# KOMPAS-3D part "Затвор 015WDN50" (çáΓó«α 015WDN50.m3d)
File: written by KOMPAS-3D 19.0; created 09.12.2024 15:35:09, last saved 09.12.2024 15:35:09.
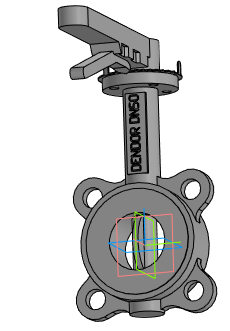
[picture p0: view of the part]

Document properties: Автор: Евгений; Полное имя файла: ..\Затвор 015WDN50.a3d

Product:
- Part/product: Затвор 015WDN50
    Масса: 4.35861

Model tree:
1. Операция без истории:1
